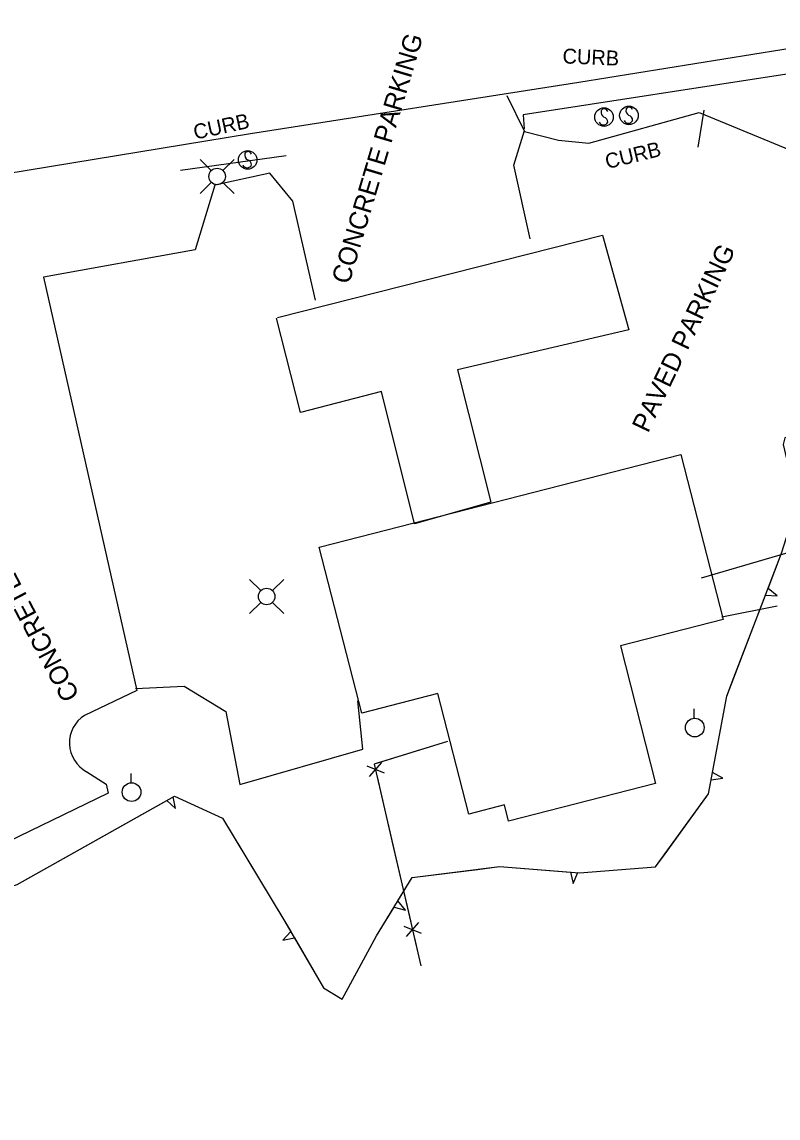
# Model space of a CAD drawing. Extents: x 978516 to 993312, y 1836504 to 1846212.
# Drawn here: x 980811.4 to 981014.1, y 1842091.9 to 1842385.6 of the extents above; entities that cross this region are included whole.
import ezdxf

# ---------------------------------------------------------------- set-up
doc = ezdxf.new("R2010")
doc.units = 0
for name, color, linetype in [('S_BUILDING', 7, 'Continuous'), ('S_CURB', 7, 'Continuous'), ('S_CURB_ANNOT', 7, 'Continuous'), ('S_EDGE_PAVEMENT', 7, 'Continuous'), ('S_FENCE', 7, 'Continuous'), ('S_MISC_STRUCTURES', 7, 'Continuous'), ('S_PARKING', 7, 'Continuous'), ('S_PARKING_ANNOT', 7, 'Continuous'), ('S_SIDEWALK', 7, 'Continuous'), ('S_SIGN', 7, 'Continuous'), ('S_TREE', 7, 'Continuous'), ('S_UTILITY_POLE', 7, 'Continuous')]:
    doc.layers.add(name, color=color, linetype=linetype)

msp = doc.modelspace()

# ---------------------------------------------------------------- linework, layer by layer
at = {"layer": 'S_BUILDING'}
msp.add_lwpolyline([(980891.13, 1842244.89), (980988.05, 1842269.71), (980999.37, 1842225.5), (980971.8, 1842218.44), (980981.25, 1842181.54), (980941.82, 1842171.44), (980940.71, 1842175.8), (980931.19, 1842173.36), (980922.92, 1842205.65), (980902.52, 1842200.43)], close=True, dxfattribs=at)
at = {"layer": 'S_CURB'}
msp.add_lwpolyline([(980994.16, 1842361.88), (980992.55, 1842352.01)], dxfattribs=at)
at = {"layer": 'S_EDGE_PAVEMENT'}
for points in [[(981061.73, 1842385.56), (980960.69, 1842369.31), (980872.65, 1842355.57)], [(980872.65, 1842355.57), (980794.78, 1842342.82), (980713.74, 1842330.18)]]:
    msp.add_lwpolyline(points, dxfattribs=at)
at = {"layer": 'S_FENCE'}
for p, q in [((980903.84, 1842186.25), (980908.47, 1842184.38)), ((980907.83, 1842187.17), (980904.48, 1842183.46)), ((980913.75, 1842143.38), (980918.38, 1842141.51)), ((980917.73, 1842144.3), (980914.39, 1842140.58))]:
    msp.add_line(p, q, dxfattribs=at)
for points in [[(980999.03, 1842226.17), (981013.86, 1842229.16)], [(980999.03, 1842226.17), (981013.86, 1842229.16)], [(980925.44, 1842192.84), (980905.83, 1842186.72), (980918.31, 1842132.73)], [(980925.44, 1842192.84), (980906.36, 1842186.89)], [(980906.6, 1842183.37), (980911.11, 1842163.88)], [(980911.11, 1842163.88), (980915.61, 1842144.39)], [(980916.51, 1842140.49), (980918.31, 1842132.73)]]:
    msp.add_lwpolyline(points, dxfattribs=at)
at = {"layer": 'S_MISC_STRUCTURES'}
msp.add_lwpolyline([(980879.9, 1842306.38), (980966.99, 1842328.48), (980974.04, 1842303.1), (980928.18, 1842292.34), (980937.11, 1842256.89), (980916.61, 1842251.13), (980907.82, 1842286.6), (980886.08, 1842280.9), (980879.67, 1842306.23)], dxfattribs=at)
at = {"layer": 'S_PARKING'}
for points in [[(980941.39, 1842365.84), (980946.08, 1842356.25), (980955.26, 1842353.92), (980963.31, 1842353.09), (980992.89, 1842361.26), (981015.88, 1842351.84), (981021.81, 1842348.65), (981027.93, 1842316.64), (981036.71, 1842280.45), (981015.89, 1842274.12), (981015.46, 1842272.33), (981021.88, 1842244.9), (980993.46, 1842236.56)], [(980947.6, 1842327.42), (980943.23, 1842347.22), (980946.08, 1842356.5)], [(980890.15, 1842310.99), (980884.07, 1842337.56), (980877.91, 1842345.01), (980863.1, 1842341.82), (980857.87, 1842324.52), (980817.18, 1842317.18), (980842.25, 1842206.43), (980828.21, 1842199.81)], [(980841.88, 1842207.03), (980854.94, 1842207.59), (980866.08, 1842200.88), (980869.86, 1842181.29), (980902.75, 1842190.79), (980901.46, 1842203.72)], [(980828.79, 1842184.69), (980834.04, 1842181.4), (980834.52, 1842178.98), (980783.67, 1842154.28), (980741.81, 1842132.74), (980740.35, 1842133.1), (980738.88, 1842133.8), (980728.87, 1842141.55), (980727.15, 1842142.2), (980724.76, 1842141.92), (980639.94, 1842110.6), (980635.81, 1842121.12), (980617.08, 1842114.71), (980622.17, 1842103.33), (980548.9, 1842075.38), (980511.23, 1842145.54)]]:
    msp.add_lwpolyline(points, dxfattribs=at)
msp.add_ellipse((980832.8, 1842192.37), major_axis=(-3.41, 8.05), ratio=0.984473, start_param=0.154839, end_param=2.251259, dxfattribs=at)
at = {"layer": 'S_SIDEWALK'}
for points in [[(981062.6, 1842379.11), (981016.38, 1842371.53), (980945.77, 1842360.63), (980946.04, 1842356.94)], [(980853.94, 1842345.88), (980882.27, 1842349.82)]]:
    msp.add_lwpolyline(points, dxfattribs=at)
at = {"layer": 'S_SIGN'}
for centre in [(980967.42, 1842360.07), (980974.1, 1842360.52), (980871.94, 1842348.6)]:
    msp.add_circle(centre, 2.49, dxfattribs=at)
for centre, radius, start, end in [((980967.5, 1842361.34), 0.95, 16.5258, 156.8957), ((980974.78, 1842361.85), 1.5, 167.1196, 241.9813), ((980974.17, 1842361.79), 0.95, 16.5258, 156.8957), ((980968.11, 1842361.39), 1.5, 167.1196, 241.9813), ((980967.01, 1842358.73), 1.4, 358.6529, 73.7063), ((980973.94, 1842359.7), 1.28, 204.641, 335.359), ((980973.68, 1842359.18), 1.4, 358.6529, 73.7063), ((980967.27, 1842359.24), 1.28, 204.641, 335.359), ((980872.62, 1842349.93), 1.5, 167.1196, 241.9813), ((980872.01, 1842349.87), 0.95, 16.5258, 156.8957), ((980871.52, 1842347.26), 1.4, 358.6529, 73.7063), ((980871.78, 1842347.78), 1.28, 204.641, 335.359)]:
    msp.add_arc(centre, radius, start, end, dxfattribs=at)
at = {"layer": 'S_TREE'}
for p, q in [((981013.83, 1842231.79), (981011.39, 1842233.79)), ((981010.69, 1842231.97), (981013.83, 1842231.79)), ((980996.16, 1842182.56), (980999.28, 1842182.95)), ((980999.28, 1842182.95), (980996.52, 1842184.49)), ((980850.3, 1842177.04), (980852.59, 1842174.89)), ((980852.59, 1842174.89), (980852.01, 1842178)), ((980958.44, 1842157.84), (980959.16, 1842154.78)), ((980959.16, 1842154.78), (980960.4, 1842157.69)), ((980911.17, 1842148.42), (980914.22, 1842147.66)), ((980914.22, 1842147.66), (980912.2, 1842150.09)), ((980883.49, 1842141.87), (980881.38, 1842139.55)), ((980881.38, 1842139.55), (980884.48, 1842140.18))]:
    msp.add_line(p, q, dxfattribs=at)
for points in [[(981011.39, 1842233.79), (981015.01, 1842243.22), (981019.44, 1842257.31)], [(980810.15, 1842154.51), (980852.32, 1842178.17), (980865.17, 1842172.26), (980881.91, 1842144.57), (980892.29, 1842126.81), (980897.24, 1842123.8), (980906.45, 1842140.72), (980916.05, 1842156.36), (980939.45, 1842159.28), (980960.81, 1842157.66), (980981.25, 1842159.21), (980995.46, 1842178.77), (981000.3, 1842204.97), (981015.01, 1842243.22)], [(981001.79, 1842208.83), (981010.69, 1842231.97)], [(980996.52, 1842184.49), (981000.3, 1842204.97), (981001.79, 1842208.83)], [(980983.34, 1842162.08), (980995.46, 1842178.77), (980996.16, 1842182.56)], [(980828.5, 1842164.81), (980850.3, 1842177.04)], [(980852.01, 1842178), (980852.32, 1842178.17), (980865.17, 1842172.26), (980870.6, 1842163.28)], [(980806.38, 1842153.34), (980810.15, 1842154.51), (980828.5, 1842164.81)], [(980870.6, 1842163.28), (980881.91, 1842144.57), (980883.49, 1842141.87)], [(980960.4, 1842157.69), (980960.81, 1842157.66), (980981.25, 1842159.21), (980983.34, 1842162.08)], [(980912.2, 1842150.09), (980916.05, 1842156.36), (980933.54, 1842158.54)], [(980933.54, 1842158.54), (980939.45, 1842159.28), (980958.44, 1842157.84)], [(980898.82, 1842126.71), (980906.45, 1842140.72), (980911.17, 1842148.42)], [(980884.48, 1842140.18), (980892.29, 1842126.81), (980897.24, 1842123.8), (980898.82, 1842126.71)]]:
    msp.add_lwpolyline(points, dxfattribs=at)
at = {"layer": 'S_UTILITY_POLE'}
for p, q in [((980862.15, 1842345.76), (980859.16, 1842348.74)), ((980865.32, 1842345.76), (980868.31, 1842348.74)), ((980862.15, 1842342.58), (980859.16, 1842339.59)), ((980865.32, 1842342.58), (980868.31, 1842339.59)), ((980875.42, 1842233.23), (980872.43, 1842236.21)), ((980878.6, 1842233.23), (980881.58, 1842236.21)), ((980875.42, 1842230.05), (980872.43, 1842227.07)), ((980878.6, 1842230.05), (980881.58, 1842227.07)), ((980991.6, 1842199.06), (980991.6, 1842201.54)), ((980840.67, 1842181.78), (980840.67, 1842184.26))]:
    msp.add_line(p, q, dxfattribs=at)
for centre, radius in [((980863.74, 1842344.17), 2.21), ((980877.02, 1842231.65), 2.21), ((980991.74, 1842196.54), 2.5), ((980840.82, 1842179.26), 2.5)]:
    msp.add_circle(centre, radius, dxfattribs=at)

# ---------------------------------------------------------------- texts
at = {"layer": 'S_CURB_ANNOT'}
for rotation, p in [(357.5465, (980956.24, 1842374.47)), (12.2213, (980857.87, 1842354.01)), (13.6022, (980968.27, 1842346.14))]:
    msp.add_text('CURB', height=4, rotation=rotation, dxfattribs=at).set_placement(p)
at = {"layer": 'S_PARKING_ANNOT'}
for s, rotation, p in [('CONCRETE PARKING', 73.3648, (980899.11, 1842315.05)), ('PAVED PARKING', 64.4882, (980979.21, 1842275.24)), ('CONCRETE PARKING', 117.8406, (980827, 1842205.19))]:
    msp.add_text(s, height=5.0005, rotation=rotation, dxfattribs=at).set_placement(p)

doc.saveas('drawing.dxf')
